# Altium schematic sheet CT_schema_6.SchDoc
size 255 x 245 mm
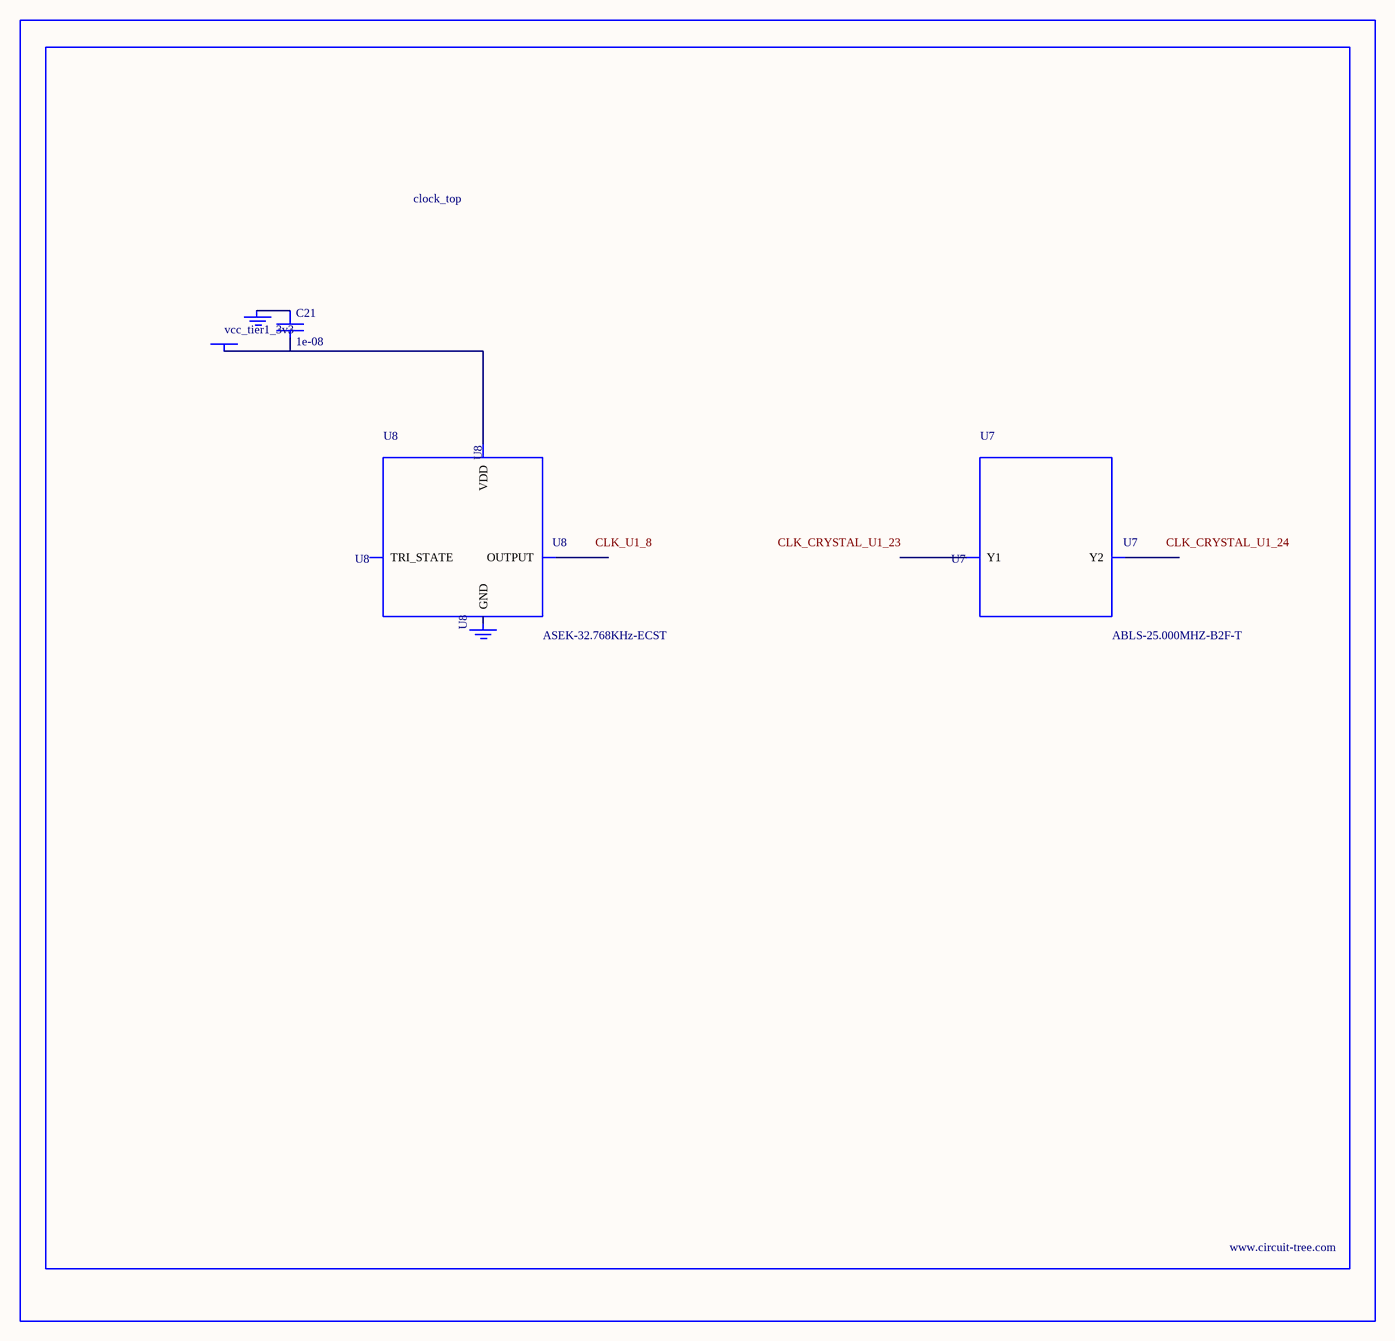
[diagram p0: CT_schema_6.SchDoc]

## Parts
BORDER5  (no value)
C21  1e-08  [C0402]
GND_INSTANCE_5_0  (no value)
GND_INSTANCE_5_1  (no value)
POWER_INSTANCE_5_0  vcc_tier1_3v3
U7  ABLS-25.000MHZ-B2F-T  [ABLS-25.000MHZ-B2F-T]
U8  ASEK-32.768KHz-ECST  [ASEK]

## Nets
NetC21_1: C21.1 GND_INSTANCE_5_0.0(GND)
NetC21_2: C21.2 POWER_INSTANCE_5_0.0(PWR) U8.4(VDD)

Not connected (* = marked no-connect by the designer): GND_INSTANCE_5_1 0(GND); U7 1(Y1) 2(Y2); U8 1(TRI_STATE) 2(GND) 3(OUTPUT)

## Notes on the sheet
- Labels drawn without touching a wire or pin: CLK_CRYSTAL_U1_23, CLK_CRYSTAL_U1_24, CLK_U1_8

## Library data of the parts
BORDER5 = BORDER_PAGE5
C21 = C0402C103K3RAC
GND_INSTANCE_5_0 GND_INSTANCE_5_1 = GND
POWER_INSTANCE_5_0 = PWR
